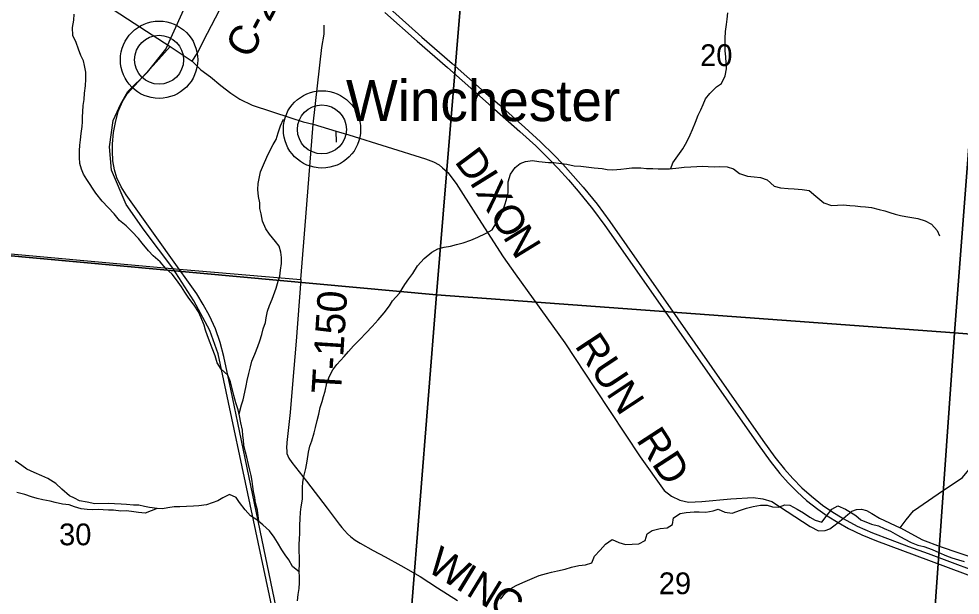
# Model space of a CAD drawing. Extents: x 0 to 42, y 0 to 22.
# Drawn here: x 5.443 to 6.349, y 17.925 to 18.48 of the extents above; entities that cross this region are included whole.
import ezdxf

# ---------------------------------------------------------------- set-up
doc = ezdxf.new("R2010")
doc.units = 0
for name, color, linetype in [('GM_X_County_Road', 7, 'Continuous'), ('GM_X_County_Road_Text', 7, 'Continuous'), ('GM_X_Minor_River', 7, 'Continuous'), ('GM_X_Rail_Line', 7, 'Continuous'), ('GM_X_Section', 7, 'Continuous'), ('GM_X_Section_Text', 7, 'Continuous'), ('GM_X_Township_Road', 7, 'Continuous'), ('GM_X_Township_Road_Text', 7, 'Continuous'), ('GM_X_Unincorporated', 7, 'Continuous'), ('GM_X_Unincorporated_Location', 7, 'Continuous'), ('GM_X_Unincorporated_Text', 7, 'Continuous'), ('GM_X_US_Route', 7, 'Continuous')]:
    doc.layers.add(name, color=color, linetype=linetype)

msp = doc.modelspace()

# ---------------------------------------------------------------- linework, layer by layer
at = {"layer": 'GM_X_County_Road'}
msp.add_line((5.58835, 18.45351), (5.60973, 18.43952), dxfattribs=at)
for points in [[(5.3521, 18.78312), (5.35279, 18.77466), (5.35365, 18.7652), (5.35773, 18.75509), (5.36289, 18.74584), (5.36687, 18.73724), (5.38061, 18.68303), (5.38536, 18.65853), (5.39072, 18.64463), (5.42336, 18.57738), (5.43241, 18.5623), (5.44039, 18.55303), (5.44707, 18.54656), (5.45202, 18.54117), (5.48111, 18.52285), (5.51967, 18.49807), (5.55371, 18.47608), (5.58835, 18.45351)], [(5.60973, 18.43952), (5.61449, 18.44686), (5.62436, 18.46627), (5.66368, 18.54178), (5.66812, 18.54945)], [(5.69734, 17.88105), (5.67859, 17.97075), (5.65348, 18.09149), (5.64712, 18.1222), (5.6401, 18.15532), (5.63648, 18.16859), (5.63198, 18.18175), (5.62617, 18.19447), (5.62036, 18.20533), (5.614, 18.21541), (5.60446, 18.2289), (5.59722, 18.2391), (5.54612, 18.31082), (5.5414, 18.31861), (5.53723, 18.32716), (5.53471, 18.33484), (5.53328, 18.3435), (5.53296, 18.35271), (5.53285, 18.35984), (5.53376, 18.37073), (5.5357, 18.38046), (5.53833, 18.3911), (5.54239, 18.40064), (5.54699, 18.40788), (5.57222, 18.43518), (5.58835, 18.45351)], [(5.60973, 18.43952), (5.61792, 18.43114), (5.62729, 18.42427), (5.63729, 18.41614), (5.64687, 18.40864), (5.65561, 18.40301), (5.66728, 18.39697), (5.70456, 18.38489), (5.71643, 18.38114), (5.72601, 18.37885), (5.74817, 18.37217), (5.76058, 18.36843), (5.83443, 18.34535), (5.84209, 18.34259), (5.84746, 18.33952), (5.85083, 18.33676), (5.85589, 18.33216), (5.86386, 18.32173), (5.88242, 18.29244), (5.90926, 18.25097), (5.92059, 18.23487), (5.96838, 18.1685), (5.99759, 18.12418), (6.04111, 18.0587), (6.06417, 18.02611), (6.07112, 18.02084), (6.07927, 18.01707), (6.08766, 18.01509), (6.10053, 18.01568), (6.12826, 18.01816), (6.14992, 18.01955), (6.15906, 18.01826), (6.1678, 18.01578), (6.20489, 17.99172), (6.21281, 17.98756), (6.21927, 17.98785), (6.22359, 17.98928), (6.22748, 17.9922), (6.23157, 17.99533), (6.23638, 17.99919), (6.24103, 18.00316), (6.24421, 18.0057)], [(6.32796, 18.02289), (6.35139, 18.03886), (6.46101, 18.17081), (6.49557, 18.21436), (6.51833, 18.25879), (6.56092, 18.30006), (6.57244, 18.30844), (6.58546, 18.31681), (6.59788, 18.32908), (6.60671, 18.33612), (6.62481, 18.3433), (6.64142, 18.35078), (6.66237, 18.3617), (6.67793, 18.37173), (6.69713, 18.38833), (6.70474, 18.39307)], [(5.59722, 18.2391), (5.71434, 18.22924), (5.71898, 18.28937), (5.72601, 18.37885)], [(5.34906, 18.2624), (5.37091, 18.26011), (5.39234, 18.25778), (5.59722, 18.2391)], [(6.24421, 18.0057), (6.24501, 18.00634), (6.24928, 18.00793), (6.25425, 18.00832), (6.25882, 18.00713), (6.26412, 18.00401), (6.27164, 17.99958), (6.29131, 17.99024), (6.29717, 17.99809), (6.30413, 18.00663), (6.32796, 18.02289)]]:
    msp.add_lwpolyline(points, dxfattribs=at)
at = {"layer": 'GM_X_Minor_River'}
for points in [[(5.67372, 17.99655), (5.67243, 18.00738), (5.67057, 18.0144), (5.66984, 18.01953), (5.66873, 18.02522), (5.668, 18.03015), (5.66726, 18.03527), (5.66634, 18.04058), (5.66504, 18.04589), (5.66393, 18.0514), (5.66226, 18.05823), (5.66096, 18.06316), (5.65947, 18.0698), (5.65893, 18.07454), (5.65857, 18.07928), (5.65802, 18.0844), (5.65635, 18.09142), (5.65525, 18.09806), (5.65395, 18.10394), (5.65171, 18.11059), (5.64966, 18.1178), (5.64818, 18.12425), (5.64651, 18.13089), (5.64408, 18.13735), (5.63749, 18.14306), (5.63355, 18.14896), (5.63188, 18.15579), (5.62889, 18.16319), (5.62702, 18.16851), (5.6244, 18.17516), (5.62235, 18.18047), (5.62104, 18.18541), (5.61824, 18.19243), (5.61562, 18.19813), (5.61149, 18.20459), (5.60642, 18.21125), (5.60247, 18.21714), (5.59947, 18.22227), (5.5944, 18.22893), (5.59027, 18.23445), (5.58424, 18.23978), (5.57879, 18.24625), (5.5722, 18.25216), (5.56769, 18.25691), (5.56148, 18.26414), (5.55791, 18.2689), (5.55151, 18.27537), (5.54606, 18.28108), (5.53966, 18.28623), (5.53439, 18.29251), (5.52875, 18.2986), (5.52292, 18.30469), (5.51691, 18.31249), (5.50827, 18.3256), (5.50489, 18.33055), (5.50302, 18.33548), (5.50134, 18.34099), (5.50099, 18.34687), (5.50121, 18.35312), (5.50161, 18.35862), (5.50201, 18.36373), (5.50279, 18.36979), (5.50376, 18.37642), (5.50416, 18.38116), (5.50399, 18.3859), (5.5042, 18.39083), (5.5048, 18.3967), (5.50558, 18.40257), (5.50598, 18.40864), (5.50677, 18.41583), (5.50736, 18.42228), (5.5072, 18.42891), (5.5061, 18.43517), (5.50498, 18.43991), (5.50255, 18.44504), (5.50031, 18.45093), (5.49788, 18.45757), (5.49469, 18.46422), (5.49435, 18.47181), (5.4957, 18.479), (5.49611, 18.48469)], [(6.07044, 18.33605), (6.07261, 18.34164), (6.07717, 18.34844), (6.08212, 18.35505), (6.08611, 18.36185), (6.08917, 18.36848), (6.09146, 18.37377), (6.09432, 18.38077), (6.097, 18.38739), (6.09929, 18.39269), (6.10158, 18.39761), (6.10406, 18.40328), (6.10805, 18.40838), (6.1145, 18.41461), (6.11924, 18.418), (6.12286, 18.42519), (6.12421, 18.43219), (6.12386, 18.4375), (6.12351, 18.44357), (6.12296, 18.44926), (6.12302, 18.4612), (6.12323, 18.46802), (6.12421, 18.47465), (6.1248, 18.47996), (6.12558, 18.48602)], [(5.65483, 18.09997), (5.657, 18.10867), (5.65872, 18.11359), (5.66026, 18.12079), (5.66161, 18.12684), (5.66258, 18.13215), (5.66412, 18.13877), (5.66585, 18.14521), (5.66719, 18.1507), (5.67006, 18.15751), (5.67273, 18.16489), (5.67465, 18.17019), (5.67656, 18.17644), (5.6781, 18.18193), (5.68039, 18.18779), (5.68098, 18.19253), (5.68233, 18.19878), (5.68424, 18.20427), (5.68672, 18.21032), (5.69036, 18.22111), (5.69247, 18.22773), (5.694, 18.23265), (5.69478, 18.23834), (5.69557, 18.24459), (5.69559, 18.25046), (5.69505, 18.25558), (5.69337, 18.26128), (5.6898, 18.26603), (5.68397, 18.27307), (5.68059, 18.27802), (5.67722, 18.28542), (5.67593, 18.29244), (5.67482, 18.29756), (5.67465, 18.30325), (5.67355, 18.30932), (5.67301, 18.31596), (5.67303, 18.32164), (5.67438, 18.32808), (5.67554, 18.33301), (5.67821, 18.33963), (5.68164, 18.347), (5.68413, 18.35249), (5.68775, 18.35911), (5.6906, 18.36402), (5.69252, 18.37046), (5.69462, 18.37708), (5.69768, 18.38351)], [(5.7162, 18.03429), (5.71717, 18.03978), (5.71909, 18.04736), (5.72025, 18.05436), (5.72162, 18.06308), (5.72296, 18.06895), (5.72488, 18.07406), (5.72718, 18.08163), (5.72852, 18.08674), (5.72987, 18.09375), (5.7316, 18.09961), (5.73295, 18.10624), (5.73468, 18.11173), (5.73602, 18.11684), (5.73755, 18.12176), (5.73929, 18.12953), (5.74196, 18.13615), (5.7452, 18.14239), (5.74881, 18.14749), (5.75584, 18.15504), (5.76021, 18.16014), (5.76514, 18.16542), (5.77122, 18.17165), (5.77729, 18.17807), (5.7828, 18.18411), (5.78868, 18.19053), (5.79457, 18.19713), (5.79951, 18.20394), (5.80256, 18.20885), (5.8092, 18.21621), (5.81453, 18.22453), (5.81814, 18.23001), (5.82214, 18.23511), (5.8267, 18.24248), (5.83316, 18.24965), (5.84036, 18.2555), (5.84605, 18.25869), (5.85229, 18.26037), (5.85853, 18.26129), (5.86421, 18.26297), (5.87064, 18.26446), (5.87783, 18.26708), (5.88484, 18.27008), (5.89203, 18.27346), (5.89847, 18.27722), (5.90247, 18.28346), (5.90514, 18.28837), (5.90875, 18.29499), (5.91086, 18.30124), (5.91239, 18.30616), (5.91393, 18.31279), (5.91377, 18.31809), (5.91398, 18.32321), (5.91628, 18.33059), (5.92065, 18.33702), (5.92558, 18.34097), (5.93051, 18.34304), (5.93731, 18.34376), (5.94336, 18.34298), (5.95261, 18.34199), (5.9579, 18.34178), (5.96281, 18.34118), (5.97037, 18.3402), (5.97735, 18.33866), (5.98378, 18.33825), (5.99171, 18.33745), (5.99681, 18.33667), (6.00437, 18.33626), (6.00927, 18.33529), (6.01475, 18.33488), (6.02231, 18.33542), (6.02799, 18.33615), (6.0329, 18.3367), (6.0416, 18.33666), (6.04707, 18.33625), (6.05312, 18.33604), (6.05841, 18.33582), (6.0637, 18.3358), (6.06937, 18.33596), (6.07826, 18.33668), (6.08355, 18.33742), (6.08998, 18.33777), (6.09565, 18.33812), (6.10094, 18.33828), (6.10661, 18.33807), (6.11266, 18.33785), (6.11757, 18.33802), (6.12494, 18.3378), (6.13079, 18.33587), (6.13682, 18.33149), (6.14436, 18.32861), (6.15079, 18.3282), (6.15683, 18.32742), (6.16325, 18.32511), (6.17002, 18.31902), (6.17606, 18.31747), (6.18362, 18.31687), (6.18929, 18.31646), (6.19703, 18.31586), (6.20383, 18.31488), (6.21005, 18.30955)], [(6.21005, 18.30955), (6.21777, 18.30307), (6.22512, 18.30057), (6.23117, 18.30092), (6.23647, 18.30128), (6.24289, 18.30068), (6.24818, 18.30009), (6.25309, 18.29969), (6.258, 18.29909), (6.26367, 18.29869), (6.27103, 18.29676), (6.2765, 18.29541), (6.28141, 18.29387), (6.28669, 18.29233), (6.29179, 18.29098), (6.29689, 18.29001), (6.30274, 18.28903), (6.30841, 18.28806), (6.31539, 18.28576), (6.32142, 18.2827), (6.32688, 18.27642), (6.32931, 18.27129)], [(5.71284, 17.94756), (5.7064, 17.95302), (5.70284, 17.95948), (5.69908, 17.96424), (5.69589, 17.96918), (5.69195, 17.97602), (5.68857, 17.98115), (5.68406, 17.98724), (5.67766, 17.99333), (5.67182, 17.9981), (5.66579, 18.00192), (5.66053, 18.00763), (5.65527, 18.01466), (5.65208, 18.0196), (5.64547, 18.02229), (5.63922, 18.01928), (5.6343, 18.01627), (5.62881, 18.01421), (5.62351, 18.01253), (5.61595, 18.01143), (5.61084, 18.01107), (5.60423, 18.01072), (5.5978, 18.01037), (5.59232, 18.0104), (5.58627, 18.00967), (5.58098, 18.00855), (5.57588, 18.00895), (5.5687, 18.00974), (5.5636, 18.0109), (5.55832, 18.01206), (5.55321, 18.01209), (5.54641, 18.01269), (5.54112, 18.01309), (5.5347, 18.01331), (5.52884, 18.01371), (5.51599, 18.01339), (5.50844, 18.01494), (5.50127, 18.0163), (5.49636, 18.01879), (5.49146, 18.02108), (5.48412, 18.02737), (5.47828, 18.03308), (5.47056, 18.03767), (5.46471, 18.04035), (5.45755, 18.0436), (5.45057, 18.04685), (5.44567, 18.05029), (5.43907, 18.05486)], [(5.71117, 17.92002), (5.71177, 17.92627), (5.71255, 17.93195), (5.71295, 17.93726), (5.71297, 17.94238), (5.71281, 17.94901), (5.71303, 17.95564), (5.71287, 17.96247), (5.71251, 17.96759), (5.71254, 17.97441), (5.71294, 17.97934), (5.71315, 17.98502), (5.71338, 17.99298), (5.71359, 17.99905), (5.714, 18.00549), (5.71459, 18.01041), (5.71575, 18.01799), (5.71596, 18.0233), (5.7158, 18.02917), (5.7162, 18.03429)], [(5.57579, 18.00896), (5.56452, 18.00446), (5.55791, 18.00505), (5.55111, 18.00603), (5.5462, 18.00662), (5.54091, 18.00646), (5.53392, 18.00725), (5.52901, 18.00727), (5.5239, 18.00748), (5.51899, 18.00788), (5.51389, 18.00771), (5.50841, 18.00793), (5.50275, 18.00852), (5.49633, 18.01064), (5.49105, 18.01255), (5.48481, 18.01296), (5.47764, 18.0147), (5.47273, 18.01586), (5.46575, 18.01722), (5.46046, 18.01838), (5.45499, 18.02011), (5.44838, 18.02241), (5.44083, 18.02415)], [(5.90639, 17.9216), (5.91133, 17.92764), (5.91664, 17.93198), (5.92175, 17.9348), (5.928, 17.93761), (5.9439, 17.94437), (5.95071, 17.94623), (5.95563, 17.94753), (5.9615, 17.94883), (5.96887, 17.95051), (5.97493, 17.95257), (5.98212, 17.95405), (5.98836, 17.95478), (5.9946, 17.95646), (5.99708, 17.96289), (6.0024, 17.96893), (6.00772, 17.97459), (6.01397, 17.97892), (6.02057, 17.97605), (6.0268, 17.97432), (6.03342, 17.97467), (6.03965, 17.97483), (6.04572, 17.97802), (6.04763, 17.98465), (6.05256, 17.98785), (6.06032, 17.98971), (6.06694, 17.99044), (6.07205, 17.99363), (6.07302, 17.99989), (6.07966, 18.00422), (6.08533, 18.00495), (6.09289, 18.00567), (6.0978, 18.00565), (6.10442, 18.00524), (6.11123, 18.00673), (6.11614, 18.00822), (6.12256, 18.00535), (6.12955, 18.00456), (6.13768, 18.00717), (6.14336, 18.00923), (6.14998, 18.01072), (6.15679, 18.01202), (6.16341, 18.01199), (6.16831, 18.01045), (6.17417, 18.01023), (6.18023, 18.01229), (6.18514, 18.01208), (6.1923, 18.00825), (6.19834, 18.00481), (6.20455, 18.00043), (6.20945, 17.99775), (6.21587, 17.99564), (6.22024, 18.0013), (6.22556, 18.00829), (6.23143, 18.01149), (6.2386, 18.00823), (6.24369, 18.00537), (6.24859, 18.00212), (6.25368, 17.99812), (6.26386, 17.9939), (6.27047, 17.99217), (6.27594, 17.98968), (6.28198, 17.98719), (6.28876, 17.98336), (6.29536, 17.97954), (6.30196, 17.9761), (6.30856, 17.97361), (6.31423, 17.97226), (6.32215, 17.96938), (6.32875, 17.9665), (6.33611, 17.96344), (6.34101, 17.96152), (6.34762, 17.9594)], [(6.34762, 17.9594), (6.3529, 17.95786)]]:
    msp.add_lwpolyline(points, dxfattribs=at)
at = {"layer": 'GM_X_Rail_Line'}
msp.add_lwpolyline([(5.70705, 17.81633), (5.63469, 18.15777), (5.6265, 18.18033), (5.6113, 18.20888), (5.591, 18.2402), (5.56344, 18.27665), (5.54618, 18.30134), (5.5321, 18.33445), (5.53012, 18.35695), (5.53347, 18.38243), (5.54108, 18.39851), (5.54777, 18.41034), (5.56646, 18.42899), (5.58423, 18.451), (5.60802, 18.50362), (5.62192, 18.53257), (5.6387, 18.57356), (5.72485, 18.79389), (5.72897, 18.81999), (5.73022, 18.85519), (5.72793, 18.89985), (5.72725, 18.96662)], dxfattribs=at)
at = {"layer": 'GM_X_Section'}
for points in [[(5.24862, 18.78217), (5.88694, 18.72342), (5.84475, 18.21447), (5.19696, 18.27399), (5.22327, 18.54106)], [(5.88694, 18.72342), (6.38282, 18.68674), (6.34385, 18.17798), (5.84475, 18.21447)], [(6.38282, 18.68674), (6.88899, 18.65144), (6.85053, 18.13693), (6.34385, 18.17798)], [(5.84475, 18.21447), (5.80483, 17.71083), (5.14624, 17.766), (5.16837, 17.9984), (5.19696, 18.27399)], [(6.34385, 18.17798), (6.30791, 17.67054), (5.80483, 17.71083), (5.84475, 18.21447)], [(6.34385, 18.17798), (6.85053, 18.13693), (6.81263, 17.63399), (6.30791, 17.67054)]]:
    msp.add_lwpolyline(points, close=True, dxfattribs=at)
at = {"layer": 'GM_X_Township_Road'}
msp.add_line((5.74858, 18.36145), (5.74817, 18.37217), dxfattribs=at)
for points in [[(5.72601, 18.37885), (5.73454, 18.4526), (5.73663, 18.46531), (5.73684, 18.47426)], [(5.71434, 18.22924), (5.7098, 18.16999), (5.70626, 18.1285), (5.70402, 18.10127), (5.70087, 18.07251), (5.70053, 18.06711), (5.70068, 18.06457), (5.70093, 18.06178), (5.70257, 18.05749), (5.70566, 18.0533), (5.71968, 18.03519), (5.73948, 18.00906), (5.75105, 17.9938), (5.75359, 17.99071), (5.75643, 17.98757), (5.75913, 17.98453), (5.76227, 17.98168), (5.76646, 17.97854), (5.77129, 17.9755), (5.78385, 17.96842), (5.79563, 17.96238), (5.81059, 17.95411), (5.82934, 17.94333), (5.8458, 17.93256), (5.86505, 17.92034)], [(6.85169, 17.63547), (6.8563, 17.65767), (6.8401, 17.67039), (6.8092, 17.68827), (6.76399, 17.71371), (6.65151, 17.7777), (6.63312, 17.78952), (6.61802, 17.80135), (6.60212, 17.81546), (6.57708, 17.8397), (6.55502, 17.86146), (6.54419, 17.87736), (6.53585, 17.88978), (6.51965, 17.90369), (6.50067, 17.91353), (6.45367, 17.93022), (6.38621, 17.95318), (6.33026, 17.97196), (6.31327, 17.97832), (6.29131, 17.99024)]]:
    msp.add_lwpolyline(points, dxfattribs=at)
at = {"layer": 'GM_X_Unincorporated'}
for centre, radius in [((5.57775, 18.44082), 0.0372), ((5.57775, 18.44082), 0.02358), ((5.73462, 18.37377), 0.0372), ((5.73462, 18.37377), 0.02358)]:
    msp.add_circle(centre, radius, dxfattribs=at)
at = {"layer": 'GM_X_Unincorporated_Location'}
for p, q in [((5.57775, 18.44082), (5.57775, 18.44082)), ((5.73462, 18.37377), (5.73462, 18.37377))]:
    msp.add_line(p, q, dxfattribs=at)
at = {"layer": 'GM_X_US_Route'}
for points in [[(5.79502, 18.48634), (5.82636, 18.45862), (5.85548, 18.43329), (5.8836, 18.40829), (5.90088, 18.3934), (5.9253, 18.37177), (5.94044, 18.35787), (5.95368, 18.34487), (5.96199, 18.33624), (5.97202, 18.32513), (5.98148, 18.31428), (5.99522, 18.29725), (6.00714, 18.28121), (6.15474, 18.07048), (6.16629, 18.05437), (6.1755, 18.04261), (6.1834, 18.03373), (6.19228, 18.02493), (6.20133, 18.01662), (6.2121, 18.00823), (6.22107, 18.00198), (6.23157, 17.99533), (6.24153, 17.98974), (6.25445, 17.98348), (6.26856, 17.97762), (6.31864, 17.95914), (6.38919, 17.93301)], [(5.79958, 18.49033), (5.83091, 18.46261), (5.86003, 18.43728), (5.88816, 18.41228), (5.90543, 18.39739), (5.92986, 18.37576), (5.94499, 18.36186), (5.95823, 18.34886), (5.96654, 18.34023), (5.97658, 18.32912), (5.98603, 18.31827), (5.99949, 18.30178), (6.0117, 18.2852), (6.15929, 18.07447), (6.17085, 18.05836), (6.18006, 18.0466), (6.18795, 18.03772), (6.19684, 18.02892), (6.20588, 18.02061), (6.21666, 18.01222), (6.22562, 18.00597), (6.23638, 17.99919), (6.24998, 17.99203), (6.26468, 17.98557), (6.28177, 17.97911), (6.29936, 17.97245), (6.31824, 17.9657), (6.33364, 17.95983), (6.36822, 17.94712)]]:
    msp.add_lwpolyline(points, dxfattribs=at)

# ---------------------------------------------------------------- texts
at = {"layer": 'GM_X_County_Road_Text'}
for s, height, rotation, p in [('C-2', 0.028409, 62.41247, (5.66563, 18.44062)), ('D', 0.02841, 306.64551, (5.86158, 18.34264)), ('I', 0.02841, 301.78445, (5.87615, 18.3231)), ('X', 0.02841, 301.33736, (5.88226, 18.31324)), ('O', 0.02841, 301.31111, (5.89526, 18.29189)), ('N', 0.02841, 301.50333, (5.90831, 18.27044)), ('RUN', 0.028409, 303.50986, (5.97745, 18.1655)), ('RD', 0.028409, 303.00296, (6.03668, 18.07499))]:
    msp.add_text(s, height=height, rotation=rotation, dxfattribs=at).set_placement(p)
at = {"layer": 'GM_X_Section_Text'}
for s, p in [('20', (6.09876, 18.43476)), ('30', (5.48147, 17.97351)), ('29', (6.05897, 17.92643))]:
    msp.add_text(s, height=0.020928, rotation=0.00001, dxfattribs=at).set_placement(p)
at = {"layer": 'GM_X_Township_Road_Text'}
for s, height, rotation, p in [('T-150', 0.028409, 86.35356, (5.75276, 18.11868)), ('W', 0.02841, 328.57647, (5.83423, 17.94952)), ('I', 0.02841, 328.58282, (5.86232, 17.93236)), ('N', 0.02841, 328.57769, (5.87228, 17.92628)), ('C', 0.02841, 328.58014, (5.89361, 17.91324))]:
    msp.add_text(s, height=height, rotation=rotation, dxfattribs=at).set_placement(p)
at = {"layer": 'GM_X_Unincorporated_Text'}
msp.add_text('Winchester', height=0.039489, rotation=0.00001, dxfattribs=at).set_placement((5.75772, 18.38179))

doc.saveas('drawing.dxf')
